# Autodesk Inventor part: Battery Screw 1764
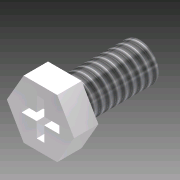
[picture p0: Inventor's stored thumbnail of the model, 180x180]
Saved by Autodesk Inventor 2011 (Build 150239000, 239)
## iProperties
Created: 2008-01
Part Number: Battery Screw 1764
Document SubType Name: Modeling
Designer: rlindsay
Density: 1 g/cm^3
Author: rlindsay
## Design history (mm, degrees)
sketch "Sketch1"
  geometry: C1 r 2.54 at (-17.947, 11.115)
  constraints: 1 centre point
  dimensions: "d0" = 5.08 diameter of C1
extrude "Extrusion1" new body sketch "Sketch1" distance "d1" = 10.16; taper "d2" = 0 deg
sketch "Sketch2"
  geometry: L1 (-2.273, -3.937)-(-4.546, 0); L2 (-4.546, 0)-(-2.273, 3.937); L3 (-2.273, 3.937)-(2.273, 3.937); L4 (2.273, 3.937)-(4.546, 0); L5 (4.546, 0)-(2.273, -3.937); L6 (2.273, -3.937)-(-2.273, -3.937); C1 r 2.54 at (0, 0) reference; 1 further point
  constraints: 12 end point, 1 coincident, 13 other
  dimensions: "d3" = 7.874 distance between parallel lines of L6 L3
extrude "Extrusion2" join sketch "Sketch2" distance "d4" = 3.302; taper "d5" = 0 deg
sketch "Sketch3"
  geometry: L1 (2.273, -3.937)-(-2.273, -3.937) reference; L2 (-2.273, 3.937)-(2.273, 3.937) reference; L3 (-0.508, 2.54)-(0.508, 2.54); L4 (0.508, 2.54)-(0.508, -2.54); L5 (0.508, -2.54)-(-0.508, -2.54); L6 (-0.508, -2.54)-(-0.508, 2.54); L7 (2.541, -0.508)-(-2.539, -0.508); L8 (-2.539, -0.508)-(-2.539, 0.508); L9 (-2.539, 0.508)-(2.541, 0.508); L10 (2.541, 0.508)-(2.541, -0.508); 2 further points
  constraints: 16 end point, 4 parallel, 2 horizontal, 2 perpendicular
  dimensions: "d6" = 5.08 distance between parallel lines of L5 L3; "d8" = 1.016 distance between parallel lines of L4 L6; "d9" = 1.016 distance between parallel lines of L7 L9; "d10" = 3.429 distance between parallel lines of L2 L9; "d11" = 3.429 distance between parallel lines of L1 L7 (derived); "d12" = 1.76503 distance from line of L2.start L6; "d13" = 1.76503 distance from line of L2.end L4 (derived); "d14" = 2.0066 distance from line of point (-4.546, 0) L8; "d16" = 5.08 distance between parallel lines of L10 L8; "d17" = 2.00551 distance from line of point (4.546, 0) L10 (derived); "d18" = 1.397 distance between parallel lines of L2 L3; "d19" = 1.397 distance between parallel lines of L1 L5 (derived)
extrude "Extrusion3" cut sketch "Sketch3" distance "d20" = 1.905; taper "d21" = 0 deg
thread "Thread1" dims "d22" = 25.4, "d23" = 0
body "Solid1"
